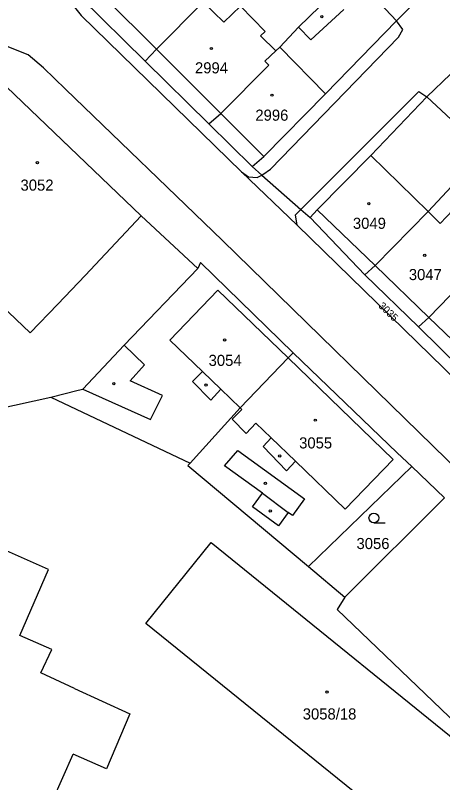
# Model space of a CAD drawing. Extents: x -527335 to -526256, y -1079142 to -1077836.
# Drawn here: x -526725 to -526659.5, y -1078831.7 to -1078714.2 of the extents above; entities that cross this region are included whole.
import ezdxf

# ---------------------------------------------------------------- set-up
doc = ezdxf.new("R2010")
doc.units = 0
for name, color, linetype in [('Hranice parcel', 7, 'Continuous'), ('Parcelní čísla', 7, 'Continuous'), ('Vnitřní kresba', 7, 'Continuous'), ('Značky budov', 7, 'Continuous'), ('Značky kultur', 7, 'Continuous')]:
    doc.layers.add(name, color=color, linetype=linetype)

msp = doc.modelspace()

# ---------------------------------------------------------------- linework, layer by layer
at = {"layer": 'Hranice parcel'}
for p, q in [((-526673.29, -1078707.97), (-526666.58, -1078715.02)), ((-526705.09, -1078721.19), (-526714.99, -1078711.45)), ((-526666.58, -1078715.02), (-526663.87, -1078712.33)), ((-526705.09, -1078721.19), (-526695.34, -1078730.81)), ((-526658.35, -1078723.2), (-526661.96, -1078726.67)), ((-526661.96, -1078726.67), (-526653.1, -1078734.98)), ((-526695.34, -1078730.81), (-526688.74, -1078737.36)), ((-526653.1, -1078734.98), (-526661.77, -1078744.22)), ((-526697.06, -1078752.95), (-526705.71, -1078744.91)), ((-526671.43, -1078753.95), (-526679.83, -1078745.15)), ((-526663.23, -1078761.88), (-526671.43, -1078753.95)), ((-526654.83, -1078770.18), (-526663.23, -1078761.88)), ((-526719.57, -1078772.65), (-526698.23, -1078782.75)), ((-526680.1, -1078798.61), (-526664.27, -1078783.3)), ((-526659.25, -1078788.06), (-526664.27, -1078783.3)), ((-526674.52, -1078803.28), (-526659.25, -1078788.06)), ((-526680.1, -1078798.61), (-526674.52, -1078803.28))]:
    msp.add_line(p, q, dxfattribs=at)
for points in [[(-526736.02, -1078622.71), (-526735.76, -1078656.09), (-526735.85, -1078660.53), (-526735.52, -1078663.69), (-526734.95, -1078666.12), (-526732.77, -1078674.37), (-526729.8, -1078686.09), (-526729.09, -1078688.53), (-526728.19, -1078690.47), (-526724.67, -1078698.8), (-526723.91, -1078700.57), (-526723.02, -1078702.2), (-526717.26, -1078711.17), (-526716.15, -1078712.7), (-526714.92, -1078714.22), (-526690.33, -1078738.18), (-526681.83, -1078746.32), (-526638.92, -1078788.12), (-526632.34, -1078794.49), (-526593.57, -1078832.2), (-526592.15, -1078831.2)], [(-526673.29, -1078707.97), (-526676.71, -1078711.19), (-526681.64, -1078715.99), (-526684.49, -1078719.05), (-526685.11, -1078719.62)], [(-526696.22, -1078712.19), (-526703.4, -1078719.37), (-526705.09, -1078721.19)], [(-526685.11, -1078719.62), (-526687.43, -1078717.35), (-526686.72, -1078716.65), (-526690.52, -1078712.81), (-526693.04, -1078715.23), (-526696.22, -1078712.19)], [(-526688.74, -1078737.36), (-526686.93, -1078735.81), (-526677.46, -1078726.23), (-526666.58, -1078715.02)], [(-526695.34, -1078730.81), (-526693.54, -1078729.21), (-526686.15, -1078721.81), (-526686.8, -1078721.19), (-526685.11, -1078719.62)], [(-526728.91, -1078722.73), (-526737.79, -1078731.81), (-526732.46, -1078736.86), (-526736.62, -1078741.14), (-526731.71, -1078745.82), (-526735.95, -1078750.27), (-526722.75, -1078762.81), (-526718.49, -1078758.42), (-526714.33, -1078754.04), (-526705.71, -1078744.91)], [(-526705.71, -1078744.91), (-526728.8, -1078722.84), (-526728.91, -1078722.73)], [(-526679.83, -1078745.15), (-526678.74, -1078743.96), (-526670.55, -1078735.68), (-526661.96, -1078726.67)], [(-526688.74, -1078737.36), (-526687.24, -1078738.67), (-526681.25, -1078743.91), (-526679.83, -1078745.15)], [(-526647.98, -1078740.34), (-526654.86, -1078747.07), (-526657.96, -1078744.05), (-526659.89, -1078746.05), (-526661.77, -1078744.22)], [(-526645, -1078743.45), (-526650.23, -1078748.74), (-526653.6, -1078752.16), (-526661.65, -1078760.47), (-526663.23, -1078761.88)], [(-526661.77, -1078744.22), (-526669.88, -1078752.51), (-526671.43, -1078753.95)], [(-526719.57, -1078772.65), (-526715.39, -1078771.61), (-526714.65, -1078771.42), (-526708.33, -1078764.68), (-526697.06, -1078752.95)], [(-526682.46, -1078765.87), (-526696.65, -1078752.02), (-526697.06, -1078752.95)], [(-526698.23, -1078782.75), (-526690.56, -1078774.31), (-526683.21, -1078766.66), (-526682.46, -1078765.87)], [(-526664.27, -1078783.3), (-526666.5, -1078781.17), (-526682.46, -1078765.87)], [(-526774.18, -1078784.68), (-526754.63, -1078780.37), (-526719.57, -1078772.65)], [(-526698.23, -1078782.75), (-526698.57, -1078783.15), (-526680.1, -1078798.61)], [(-526659.11, -1078844.46), (-526705.02, -1078807.32), (-526694.99, -1078794.92), (-526649.08, -1078832.06), (-526659.11, -1078844.46)], [(-526674.52, -1078803.28), (-526675.67, -1078805.16), (-526643.83, -1078835.71)]]:
    msp.add_lwpolyline(points, dxfattribs=at)
at = {"layer": 'Vnitřní kresba'}
for p, q in [((-526713.16, -1078709.62), (-526703.4, -1078719.37)), ((-526679.72, -1078717.92), (-526674.67, -1078713.29)), ((-526665.65, -1078716.37), (-526666.58, -1078715.02)), ((-526681.64, -1078715.99), (-526679.72, -1078717.92)), ((-526666.28, -1078717.56), (-526665.65, -1078716.37)), ((-526685.93, -1078737.75), (-526666.28, -1078717.56)), ((-526723.03, -1078720.23), (-526726.79, -1078718.76)), ((-526693.54, -1078729.21), (-526703.4, -1078719.37)), ((-526684.49, -1078719.05), (-526677.46, -1078726.23)), ((-526720.69, -1078722.22), (-526723.03, -1078720.23)), ((-526717.32, -1078725.48), (-526720.69, -1078722.22)), ((-526693.26, -1078748.65), (-526717.32, -1078725.48)), ((-526681.25, -1078743.91), (-526663.2, -1078725.86)), ((-526663.2, -1078725.86), (-526661.96, -1078726.67)), ((-526693.54, -1078729.21), (-526686.93, -1078735.81)), ((-526670.55, -1078735.68), (-526661.77, -1078744.22)), ((-526690.33, -1078738.18), (-526689.3, -1078738.9)), ((-526687.94, -1078739.04), (-526687.24, -1078738.67)), ((-526687.24, -1078738.67), (-526687.06, -1078738.58)), ((-526687.06, -1078738.58), (-526685.93, -1078737.75)), ((-526689.3, -1078738.9), (-526687.94, -1078739.04)), ((-526682.09, -1078744.75), (-526681.25, -1078743.91)), ((-526681.83, -1078746.32), (-526682.09, -1078744.75)), ((-526678.74, -1078743.96), (-526669.88, -1078752.51)), ((-526649.54, -1078791.39), (-526693.26, -1078748.65)), ((-526669.88, -1078752.51), (-526661.65, -1078760.47)), ((-526693.96, -1078756.27), (-526701.33, -1078763.94)), ((-526683.21, -1078766.66), (-526693.96, -1078756.27)), ((-526661.65, -1078760.47), (-526653.11, -1078768.71)), ((-526705.22, -1078767.71), (-526708.33, -1078764.68)), ((-526701.33, -1078763.94), (-526696.31, -1078768.76)), ((-526667.13, -1078782.2), (-526683.21, -1078766.66)), ((-526707.41, -1078770.17), (-526705.22, -1078767.71)), ((-526696.31, -1078768.76), (-526697.84, -1078770.25)), ((-526696.31, -1078768.76), (-526693.52, -1078771.46)), ((-526702.45, -1078772.41), (-526707.41, -1078770.17)), ((-526697.84, -1078770.25), (-526695.03, -1078773.14)), ((-526714.65, -1078771.42), (-526704.29, -1078776.09)), ((-526695.03, -1078773.14), (-526693.52, -1078771.46)), ((-526693.52, -1078771.46), (-526690.56, -1078774.31)), ((-526704.29, -1078776.09), (-526702.45, -1078772.41)), ((-526691.8, -1078776.05), (-526690.28, -1078774.58)), ((-526690.28, -1078774.58), (-526690.56, -1078774.31)), ((-526689.64, -1078778.23), (-526691.8, -1078776.05)), ((-526688.14, -1078776.64), (-526689.64, -1078778.23)), ((-526685.81, -1078778.89), (-526688.14, -1078776.64)), ((-526685.81, -1078778.89), (-526687.01, -1078780.22)), ((-526685.81, -1078778.89), (-526682.06, -1078782.49)), ((-526692.95, -1078783.19), (-526690.93, -1078780.81)), ((-526690.93, -1078780.81), (-526680.69, -1078788.25)), ((-526687.01, -1078780.22), (-526683.46, -1078783.94)), ((-526674.46, -1078789.82), (-526667.13, -1078782.2)), ((-526687.15, -1078787.36), (-526692.95, -1078783.19)), ((-526683.46, -1078783.94), (-526682.06, -1078782.49)), ((-526682.06, -1078782.49), (-526674.46, -1078789.82)), ((-526688.69, -1078789.47), (-526687.15, -1078787.36)), ((-526687.15, -1078787.36), (-526683.21, -1078790.31)), ((-526680.69, -1078788.25), (-526682.54, -1078790.8)), ((-526719.94, -1078799.06), (-526740.14, -1078790.15)), ((-526684.7, -1078792.37), (-526688.69, -1078789.47)), ((-526683.21, -1078790.31), (-526684.7, -1078792.37)), ((-526682.54, -1078790.8), (-526683.21, -1078790.31)), ((-526724.33, -1078809.18), (-526719.94, -1078799.06)), ((-526719.43, -1078811.33), (-526724.33, -1078809.18)), ((-526721.12, -1078814.9), (-526719.43, -1078811.33)), ((-526715.92, -1078817.28), (-526721.12, -1078814.9)), ((-526715.92, -1078817.28), (-526707.46, -1078821.16)), ((-526707.46, -1078821.16), (-526711.06, -1078829.56)), ((-526723.31, -1078843.53), (-526716.16, -1078827.32)), ((-526711.06, -1078829.56), (-526716.16, -1078827.32))]:
    msp.add_line(p, q, dxfattribs=at)
at = {"layer": 'Značky budov'}
for centre in [(-526678.04, -1078714.38), (-526694.96, -1078719.27), (-526685.69, -1078726.42), (-526721.62, -1078736.74), (-526670.84, -1078743.03), (-526662.27, -1078750.94), (-526692.95, -1078763.9), (-526709.91, -1078770.59), (-526695.77, -1078770.82), (-526679.04, -1078776.19), (-526684.49, -1078781.66), (-526686.68, -1078785.87), (-526685.95, -1078790.08), (-526677.23, -1078817.83)]:
    msp.add_circle(centre, 0.175, dxfattribs=at)
at = {"layer": 'Značky kultur'}
msp.add_line((-526670.07, -1078791.91), (-526668.32, -1078791.91), dxfattribs=at)
msp.add_circle((-526670.07, -1078791.16), 0.75, dxfattribs=at)

# ---------------------------------------------------------------- texts
at = {"layer": 'Parcelní čísla'}
for s, p in [('2994', (-526697.48, -1078723.08)), ('2996', (-526688.23, -1078730.33)), ('3052', (-526724.21, -1078741.04)), ('3049', (-526673.28, -1078746.89)), ('3047', (-526664.71, -1078754.74)), ('3054', (-526695.39, -1078767.88)), ('3055', (-526681.52, -1078780.52)), ('3056', (-526672.73, -1078795.93)), ('3058/18', (-526680.97, -1078822.03))]:
    msp.add_text(s, height=1.7, dxfattribs=at).set_placement(p)
msp.add_text('3035', height=1.14, rotation=316, dxfattribs=at).set_placement((-526669.45, -1078758.8))

doc.saveas('drawing.dxf')
